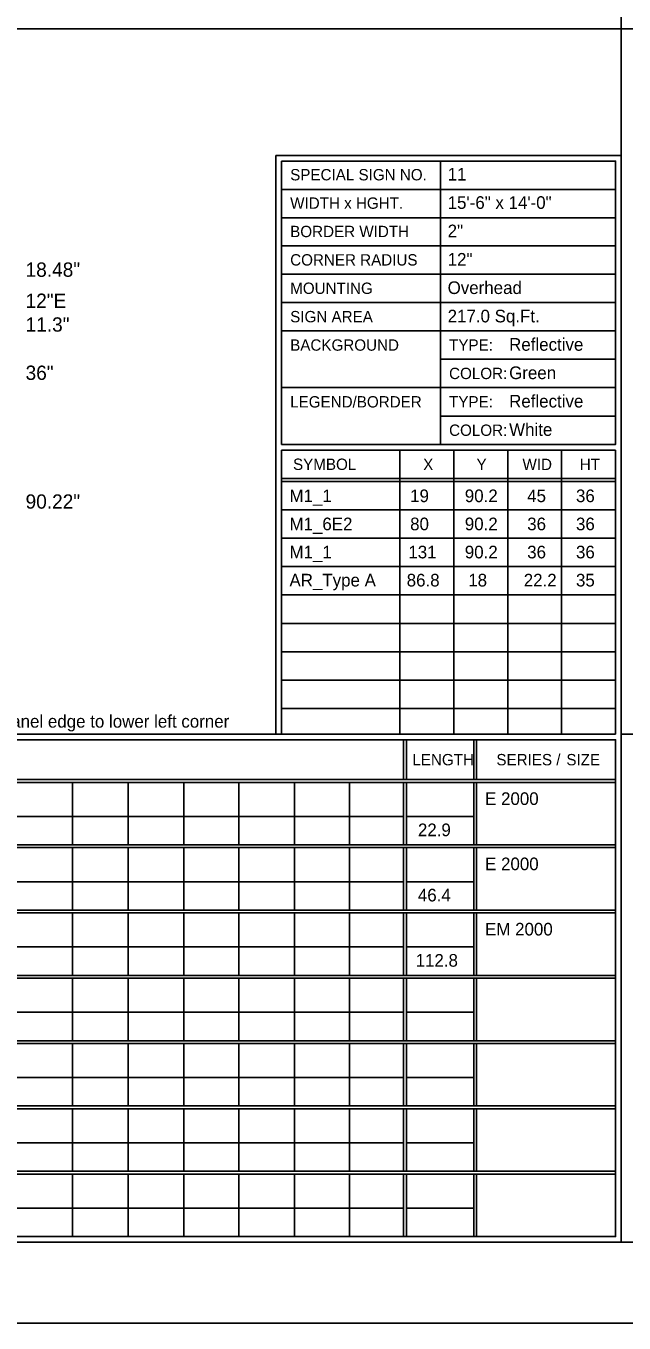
# Model space of a CAD drawing. Extents: x 2150010 to 2150174, y 145114 to 145224.
# Drawn here: x 2150052 to 2150076.4, y 145114.1 to 145167.1 of the extents above; entities that cross this region are included whole.
import ezdxf

# ---------------------------------------------------------------- set-up
doc = ezdxf.new("R2010")
doc.units = 0
for name, color, linetype in [('BORDER', 7, 'Continuous'), ('GSDIMS', 7, 'Continuous'), ('GSSHT', 7, 'Continuous'), ('Level 1', 7, 'Continuous'), ('PDF', 7, 'Continuous')]:
    doc.layers.add(name, color=color, linetype=linetype)

msp = doc.modelspace()

# ---------------------------------------------------------------- linework, layer by layer
at = {"layer": 'BORDER'}
for p, q in [((2150017.557, 145117.388), (2150171.536, 145117.388)), ((2150010.458, 145114.088), (2150174.061, 145114.088))]:
    msp.add_line(p, q, dxfattribs=at)
at = {"layer": 'Level 1'}
for p, q in [((2150076.316, 145216.512), (2150076.316, 145117.388)), ((2150135.447, 145166.95), (2150017.557, 145166.95)), ((2150062.21, 145161.778), (2150076.316, 145161.778)), ((2150068.935, 145161.546), (2150068.935, 145149.975)), ((2150062.442, 145160.387), (2150076.084, 145160.387)), ((2150062.442, 145159.227), (2150076.084, 145159.227)), ((2150062.442, 145158.091), (2150076.084, 145158.091)), ((2150062.442, 145156.932), (2150076.084, 145156.932)), ((2150062.442, 145155.772), (2150076.084, 145155.772)), ((2150062.442, 145154.613), (2150076.084, 145154.613)), ((2150068.935, 145153.453), (2150076.084, 145153.453)), ((2150062.442, 145152.294), (2150076.084, 145152.294)), ((2150068.935, 145151.134), (2150076.084, 145151.134)), ((2150062.442, 145138.143), (2150062.442, 145149.743)), ((2150062.442, 145149.743), (2150076.084, 145149.743)), ((2150067.272, 145149.737), (2150067.272, 145148.578)), ((2150069.475, 145149.737), (2150069.475, 145148.578)), ((2150071.678, 145149.737), (2150071.678, 145148.578)), ((2150073.881, 145149.737), (2150073.881, 145148.578)), ((2150076.084, 145149.743), (2150076.084, 145138.143)), ((2150062.442, 145148.578), (2150076.084, 145148.578)), ((2150062.442, 145148.462), (2150076.084, 145148.462)), ((2150067.272, 145148.578), (2150067.272, 145138.143)), ((2150069.475, 145148.578), (2150069.475, 145138.143)), ((2150071.678, 145148.578), (2150071.678, 145138.143)), ((2150073.881, 145148.578), (2150073.881, 145138.143)), ((2150062.442, 145147.303), (2150076.084, 145147.303)), ((2150062.442, 145146.143), (2150076.084, 145146.143)), ((2150062.442, 145144.984), (2150076.084, 145144.984)), ((2150062.442, 145143.824), (2150076.084, 145143.824)), ((2150062.442, 145142.665), (2150076.084, 145142.665)), ((2150062.442, 145141.505), (2150076.084, 145141.505)), ((2150062.442, 145140.346), (2150076.084, 145140.346)), ((2150062.442, 145139.186), (2150076.084, 145139.186)), ((2150017.557, 145138.143), (2150062.583, 145138.143)), ((2150076.084, 145138.143), (2150062.442, 145138.143)), ((2150076.316, 145138.143), (2150121.342, 145138.143)), ((2150067.426, 145137.911), (2150067.426, 145136.288)), ((2150067.542, 145137.911), (2150067.542, 145136.288)), ((2150070.29, 145137.911), (2150070.29, 145136.288)), ((2150070.405, 145137.911), (2150070.405, 145136.288)), ((2150017.789, 145136.288), (2150076.084, 145136.288)), ((2150017.789, 145136.172), (2150076.084, 145136.172)), ((2150053.895, 145136.172), (2150053.895, 145133.621)), ((2150056.168, 145136.172), (2150056.168, 145133.621)), ((2150058.441, 145136.172), (2150058.441, 145133.621)), ((2150060.69, 145136.172), (2150060.69, 145133.621)), ((2150062.962, 145136.172), (2150062.962, 145133.621)), ((2150065.212, 145136.172), (2150065.212, 145133.621)), ((2150067.426, 145136.172), (2150067.426, 145133.621)), ((2150067.542, 145136.172), (2150067.542, 145133.621)), ((2150070.29, 145136.172), (2150070.29, 145133.621)), ((2150070.405, 145136.172), (2150070.405, 145133.621)), ((2150017.789, 145134.78), (2150067.426, 145134.78)), ((2150067.542, 145134.78), (2150070.29, 145134.78)), ((2150017.789, 145133.621), (2150076.084, 145133.621)), ((2150017.789, 145133.505), (2150076.084, 145133.505)), ((2150053.895, 145133.505), (2150053.895, 145130.954)), ((2150056.168, 145133.505), (2150056.168, 145130.954)), ((2150058.441, 145133.505), (2150058.441, 145130.954)), ((2150060.69, 145133.505), (2150060.69, 145130.954)), ((2150062.962, 145133.505), (2150062.962, 145130.954)), ((2150065.212, 145133.505), (2150065.212, 145130.954)), ((2150067.426, 145133.505), (2150067.426, 145130.954)), ((2150067.542, 145133.505), (2150067.542, 145130.954)), ((2150070.29, 145133.505), (2150070.29, 145130.954)), ((2150070.405, 145133.505), (2150070.405, 145130.954)), ((2150017.789, 145132.113), (2150067.426, 145132.113)), ((2150067.542, 145132.113), (2150070.29, 145132.113)), ((2150017.789, 145130.954), (2150076.084, 145130.954)), ((2150017.789, 145130.838), (2150076.084, 145130.838)), ((2150053.895, 145130.838), (2150053.895, 145128.287)), ((2150056.168, 145130.838), (2150056.168, 145128.287)), ((2150058.441, 145130.838), (2150058.441, 145128.287)), ((2150060.69, 145130.838), (2150060.69, 145128.287)), ((2150062.962, 145130.838), (2150062.962, 145128.287)), ((2150065.212, 145130.838), (2150065.212, 145128.287)), ((2150067.426, 145130.838), (2150067.426, 145128.287)), ((2150067.542, 145130.838), (2150067.542, 145128.287)), ((2150070.29, 145130.838), (2150070.29, 145128.287)), ((2150070.405, 145130.838), (2150070.405, 145128.287)), ((2150017.789, 145129.447), (2150067.426, 145129.447)), ((2150067.542, 145129.447), (2150070.29, 145129.447)), ((2150017.789, 145128.287), (2150076.084, 145128.287)), ((2150017.789, 145128.171), (2150076.084, 145128.171)), ((2150053.895, 145128.171), (2150053.895, 145125.62)), ((2150056.168, 145128.171), (2150056.168, 145125.62)), ((2150058.441, 145128.171), (2150058.441, 145125.62)), ((2150060.69, 145128.171), (2150060.69, 145125.62)), ((2150062.962, 145128.171), (2150062.962, 145125.62)), ((2150065.212, 145128.171), (2150065.212, 145125.62)), ((2150067.426, 145128.171), (2150067.426, 145125.62)), ((2150067.542, 145128.171), (2150067.542, 145125.62)), ((2150070.29, 145128.171), (2150070.29, 145125.62)), ((2150070.405, 145128.171), (2150070.405, 145125.62)), ((2150017.789, 145126.78), (2150067.426, 145126.78)), ((2150067.542, 145126.78), (2150070.29, 145126.78)), ((2150017.789, 145125.62), (2150076.084, 145125.62)), ((2150017.789, 145125.504), (2150076.084, 145125.504)), ((2150053.895, 145125.504), (2150053.895, 145122.954)), ((2150056.168, 145125.504), (2150056.168, 145122.954)), ((2150058.441, 145125.504), (2150058.441, 145122.954)), ((2150060.69, 145125.504), (2150060.69, 145122.954)), ((2150062.962, 145125.504), (2150062.962, 145122.954)), ((2150065.212, 145125.504), (2150065.212, 145122.954)), ((2150067.426, 145125.504), (2150067.426, 145122.954)), ((2150067.542, 145125.504), (2150067.542, 145122.954)), ((2150070.29, 145125.504), (2150070.29, 145122.954)), ((2150070.405, 145125.504), (2150070.405, 145122.954)), ((2150017.789, 145124.113), (2150067.426, 145124.113)), ((2150067.542, 145124.113), (2150070.29, 145124.113)), ((2150017.789, 145122.954), (2150076.084, 145122.954)), ((2150017.789, 145122.838), (2150076.084, 145122.838)), ((2150053.895, 145122.838), (2150053.895, 145120.287)), ((2150056.168, 145122.838), (2150056.168, 145120.287)), ((2150058.441, 145122.838), (2150058.441, 145120.287)), ((2150060.69, 145122.838), (2150060.69, 145120.287)), ((2150062.962, 145122.838), (2150062.962, 145120.287)), ((2150065.212, 145122.838), (2150065.212, 145120.287)), ((2150067.426, 145122.838), (2150067.426, 145120.287)), ((2150067.542, 145122.838), (2150067.542, 145120.287)), ((2150070.29, 145122.838), (2150070.29, 145120.287)), ((2150070.405, 145122.838), (2150070.405, 145120.287)), ((2150017.789, 145121.446), (2150067.426, 145121.446)), ((2150067.542, 145121.446), (2150070.29, 145121.446)), ((2150017.789, 145120.287), (2150076.084, 145120.287)), ((2150017.789, 145120.171), (2150076.084, 145120.171)), ((2150053.895, 145120.171), (2150053.895, 145117.62)), ((2150056.168, 145120.171), (2150056.168, 145117.62)), ((2150058.441, 145120.171), (2150058.441, 145117.62)), ((2150060.69, 145120.171), (2150060.69, 145117.62)), ((2150062.962, 145120.171), (2150062.962, 145117.62)), ((2150065.212, 145120.171), (2150065.212, 145117.62)), ((2150067.426, 145120.171), (2150067.426, 145117.62)), ((2150067.542, 145120.171), (2150067.542, 145117.62)), ((2150070.29, 145120.171), (2150070.29, 145117.62)), ((2150070.405, 145120.171), (2150070.405, 145117.62)), ((2150017.789, 145118.779), (2150067.426, 145118.779)), ((2150067.542, 145118.779), (2150070.29, 145118.779))]:
    msp.add_line(p, q, dxfattribs=at)
msp.add_lwpolyline([(2150062.21, 145138.143), (2150062.21, 145161.778)], dxfattribs=at)
for points in [[(2150062.442, 145161.546), (2150076.084, 145161.546), (2150076.084, 145149.975), (2150062.442, 145149.975)], [(2150017.789, 145137.911), (2150076.084, 145137.911), (2150076.084, 145117.62), (2150017.789, 145117.62)]]:
    msp.add_lwpolyline(points, close=True, dxfattribs=at)
at = {"layer": 'PDF'}
msp.add_lwpolyline([(2150010.458, 145114.088), (2150174.061, 145114.088), (2150174.061, 145219.948), (2150010.458, 145219.948)], close=True, dxfattribs=at)

# ---------------------------------------------------------------- texts
at = {"layer": 'GSDIMS'}
for s, p in [('18.48"', (2150051.978, 145156.821)), ('12"E', (2150051.978, 145155.551)), ('11.3"', (2150051.978, 145154.58)), ('36"', (2150051.978, 145152.609)), ('90.22"', (2150051.978, 145147.35))]:
    msp.add_text(s, height=0.5833, dxfattribs=at).set_placement(p)
at = {"layer": 'GSSHT'}
for s, p in [('11', (2150069.224, 145160.753)), ('Overhead', (2150069.224, 145156.117))]:
    msp.add_text(s, height=0.5165, dxfattribs=at).set_placement(p)
at = {"layer": 'Level 1'}
for s, height, p in [('SPECIAL SIGN NO.', 0.46374, (2150062.79, 145160.758)), ('WIDTH x HGHT.', 0.46374, (2150062.79, 145159.598)), ('15\'-6" x 14\'-0"', 0.51652, (2150069.224, 145159.594)), ('BORDER WIDTH', 0.46374, (2150062.79, 145158.439)), ('2"', 0.5165, (2150069.224, 145158.435)), ('CORNER RADIUS', 0.46374, (2150062.79, 145157.28)), ('12"', 0.5165, (2150069.224, 145157.276)), ('MOUNTING', 0.4637, (2150062.79, 145156.12)), ('SIGN AREA', 0.4638, (2150062.79, 145154.961)), ('217.0 Sq.Ft.', 0.51652, (2150069.224, 145154.958)), ('BACKGROUND', 0.4637, (2150062.79, 145153.801)), ('TYPE:', 0.4637, (2150069.283, 145153.801)), ('Reflective', 0.5165, (2150071.736, 145153.8)), ('COLOR:', 0.4637, (2150069.283, 145152.642)), ('Green', 0.5165, (2150071.736, 145152.641)), ('LEGEND/BORDER', 0.46374, (2150062.79, 145151.482)), ('TYPE:', 0.4637, (2150069.283, 145151.482)), ('Reflective', 0.5165, (2150071.736, 145151.482)), ('White', 0.5165, (2150071.736, 145150.323)), ('COLOR:', 0.4637, (2150069.283, 145150.323)), ('SYMBOL', 0.4637, (2150062.906, 145148.931)), ('X', 0.464, (2150068.223, 145148.926)), ('Y', 0.464, (2150070.403, 145148.926)), ('WID', 0.4637, (2150072.281, 145148.926)), ('HT', 0.4637, (2150074.623, 145148.926)), ('M1_1', 0.5165, (2150062.761, 145147.616)), ('19', 0.5165, (2150067.692, 145147.616)), ('90.2', 0.5165, (2150069.925, 145147.616)), ('45', 0.5165, (2150072.474, 145147.616)), ('36', 0.5165, (2150074.467, 145147.616)), ('M1_6E2', 0.5165, (2150062.761, 145146.468)), ('80', 0.5165, (2150067.692, 145146.468)), ('90.2', 0.5165, (2150069.925, 145146.468)), ('36', 0.5165, (2150072.474, 145146.468)), ('36', 0.5165, (2150074.467, 145146.468)), ('M1_1', 0.5165, (2150062.761, 145145.32)), ('131', 0.5165, (2150067.619, 145145.32)), ('90.2', 0.5165, (2150069.925, 145145.32)), ('36', 0.5165, (2150072.474, 145145.32)), ('36', 0.5165, (2150074.467, 145145.32)), ('AR_Type A', 0.5165, (2150062.761, 145144.172)), ('86.8', 0.5165, (2150067.551, 145144.172)), ('18', 0.5165, (2150070.066, 145144.172)), ('22.2', 0.5165, (2150072.333, 145144.172)), ('35', 0.5165, (2150074.467, 145144.172)), ('Letter locations are panel edge to lower left corner', 0.51652, (2150044.943, 145138.406)), ('LENGTH', 0.4638, (2150067.783, 145136.867)), ('LENGTH', 0.4638, (2150067.783, 145136.867)), ('SERIES /', 0.4638, (2150071.216, 145136.867)), ('SIZE', 0.4638, (2150074.074, 145136.867)), ('E 2000', 0.5165, (2150070.753, 145135.248)), ('22.9', 0.5165, (2150068.009, 145133.973)), ('E 2000', 0.5165, (2150070.753, 145132.583)), ('46.4', 0.5165, (2150068.007, 145131.308)), ('EM 2000', 0.5165, (2150070.753, 145129.917)), ('112.8', 0.5165, (2150067.915, 145128.643))]:
    msp.add_text(s, height=height, dxfattribs=at).set_placement(p)

doc.saveas('drawing.dxf')
